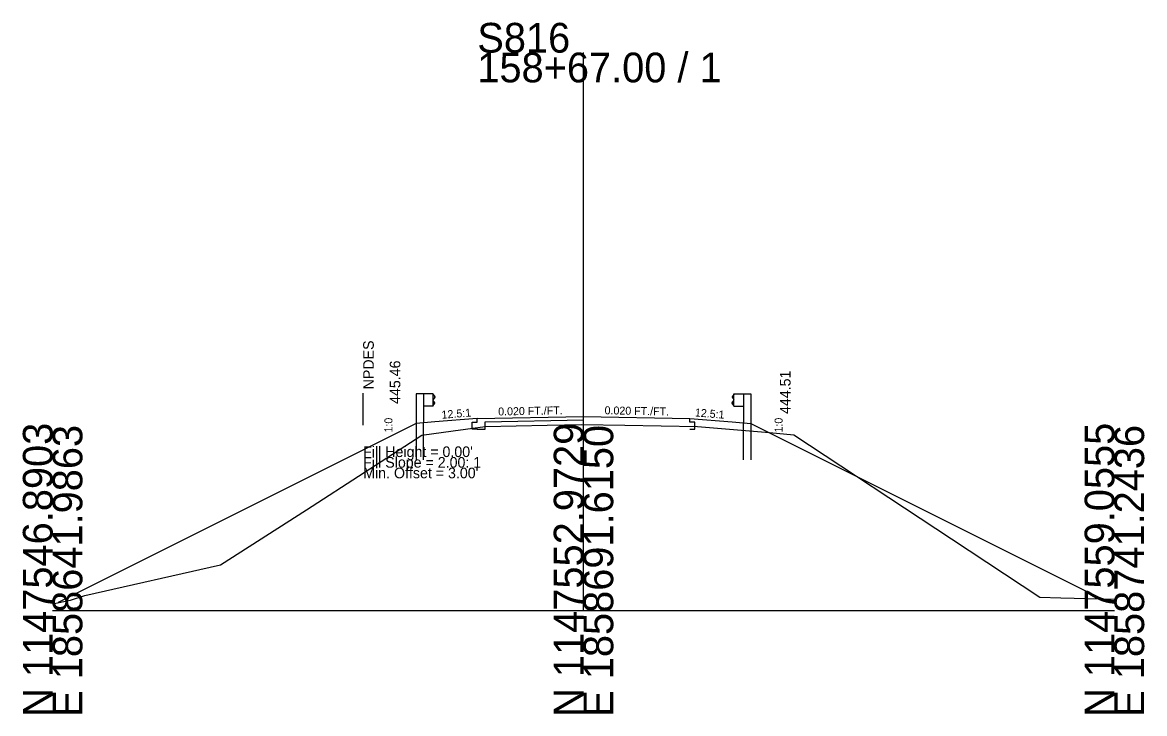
# Model space of a CAD drawing. Extents: x -76 to 4323, y -10 to 2055.
# Drawn here: x 997.2 to 1102.8, y -9.7 to 55.4 of the extents above; entities that cross this region are included whole.
import ezdxf

# ---------------------------------------------------------------- set-up
doc = ezdxf.new("R2010")
doc.units = 0
for name, color, linetype in [('Default', 7, 'Continuous'), ('RD_GPK_XS_Cell', 7, 'Continuous'), ('RD_XS_Base', 7, 'Continuous'), ('RD_XS_Buildup', 7, 'Continuous'), ('RD_XS_EarthShd', 7, 'Continuous'), ('RD_XS_ExGround', 7, 'Continuous'), ('RD_XS_GR', 7, 'Continuous'), ('RD_XS_NPDES', 7, 'Continuous'), ('RD_XS_Pave', 7, 'Continuous'), ('RD_XS_TieSlope', 7, 'Continuous'), ('RD_XS_TX_Elev_PR', 7, 'Continuous'), ('RD_XS_TX_ShdSlope', 7, 'Continuous'), ('RD_XS_TX_Slope', 7, 'Continuous'), ('RD_XS_TX_Warning', 7, 'Continuous')]:
    doc.layers.add(name, color=color, linetype=linetype)

msp = doc.modelspace()

# ---------------------------------------------------------------- linework, layer by layer
at = {"layer": 'Default'}
for p, q in [((1040, 18.08), (1050, 18.28)), ((1050, 18.28), (1060, 18.08))]:
    msp.add_line(p, q, dxfattribs=at)
at = {"layer": 'RD_GPK_XS_Cell'}
for p, q in [((1050, 0), (1050, 52.54)), ((1000, 0), (1050, 0)), ((1050, 0), (1100, 0))]:
    msp.add_line(p, q, dxfattribs=at)
at = {"layer": 'RD_XS_Base'}
for p, q in [((1040, 17.08), (1040.73, 17.09)), ((1040, 17.08), (1040.73, 17.09)), ((1040.73, 17.09), (1040.73, 17.33)), ((1040.73, 17.09), (1040.73, 17.33))]:
    msp.add_line(p, q, dxfattribs=at)
at = {"layer": 'RD_XS_Buildup'}
for p, q in [((1040.73, 17.76), (1050, 17.95)), ((1040.73, 17.76), (1050, 17.95)), ((1040.73, 17.33), (1040.73, 17.76)), ((1040.73, 17.33), (1040.73, 17.76))]:
    msp.add_line(p, q, dxfattribs=at)
at = {"layer": 'RD_XS_EarthShd'}
for p, q in [((1040, 18.08), (1036, 17.76)), ((1040, 18.08), (1036, 17.76)), ((1060, 18.08), (1064, 17.76)), ((1060, 18.08), (1064, 17.76)), ((1036, 17.76), (1034.25, 17.62)), ((1064, 17.76), (1065.75, 17.62))]:
    msp.add_line(p, q, dxfattribs=at)
at = {"layer": 'RD_XS_ExGround'}
for p, q in [((1034.78, 16.53), (1037.73, 16.92)), ((1037.73, 16.92), (1040.73, 17.33)), ((1040.73, 17.33), (1046.57, 17.46)), ((1046.57, 17.46), (1049.85, 17.51)), ((1049.85, 17.51), (1053.88, 17.46)), ((1053.88, 17.46), (1060.75, 17.34)), ((1060.75, 17.34), (1067.52, 16.76)), ((1023.9, 9.49), (1034.78, 16.53)), ((1067.52, 16.76), (1069.82, 16.56)), ((1069.82, 16.56), (1084.67, 6.77)), ((1015.82, 4.3), (1023.9, 9.49)), ((1084.67, 6.77), (1092.97, 1.26)), ((1003.04, 1.42), (1015.82, 4.3)), ((1001.68, 0.99), (1003.04, 1.42)), ((1092.97, 1.26), (1094.95, 1.21)), ((1094.95, 1.21), (1100, 1.08)), ((1000, 0.65), (1001.68, 0.99))]:
    msp.add_line(p, q, dxfattribs=at)
at = {"layer": 'RD_XS_GR'}
for p, q in [((1034.25, 20.42), (1034.25, 17.62)), ((1034.92, 20.42), (1034.25, 20.42)), ((1034.25, 20.42), (1034.25, 17.62)), ((1034.92, 20.42), (1034.25, 20.42)), ((1034.92, 20.42), (1034.92, 17.67)), ((1035.83, 20.42), (1034.92, 20.42)), ((1034.92, 20.42), (1034.92, 17.67)), ((1035.83, 20.42), (1034.92, 20.42)), ((1035.83, 19.25), (1035.83, 20.42)), ((1035.83, 19.25), (1035.83, 20.42)), ((1035.83, 20.34), (1036, 20.14)), ((1035.83, 20.34), (1036, 20.14)), ((1036, 20.09), (1035.83, 19.89)), ((1036, 20.09), (1035.83, 19.89)), ((1036, 20.14), (1036, 20.09)), ((1036, 20.14), (1036, 20.09)), ((1064.17, 20.34), (1064, 20.14)), ((1064.17, 20.34), (1064, 20.14)), ((1064, 20.14), (1064, 20.09)), ((1064, 20.14), (1064, 20.09)), ((1064, 20.09), (1064.17, 19.89)), ((1064, 20.09), (1064.17, 19.89)), ((1064.17, 20.42), (1065.08, 20.42)), ((1064.17, 19.25), (1064.17, 20.42)), ((1064.17, 20.42), (1065.08, 20.42)), ((1064.17, 19.25), (1064.17, 20.42)), ((1065.08, 20.42), (1065.75, 20.42)), ((1065.08, 20.42), (1065.08, 17.67)), ((1065.08, 20.42), (1065.75, 20.42)), ((1065.08, 20.42), (1065.08, 17.67)), ((1065.75, 20.42), (1065.75, 17.62)), ((1065.75, 20.42), (1065.75, 17.62)), ((1035.83, 19.25), (1034.92, 19.25)), ((1035.83, 19.25), (1034.92, 19.25)), ((1036, 19.57), (1035.83, 19.77)), ((1036, 19.57), (1035.83, 19.77)), ((1035.83, 19.32), (1036, 19.52)), ((1035.83, 19.32), (1036, 19.52)), ((1036, 19.52), (1036, 19.57)), ((1036, 19.52), (1036, 19.57)), ((1064, 19.57), (1064.17, 19.77)), ((1064, 19.57), (1064.17, 19.77)), ((1064, 19.52), (1064, 19.57)), ((1064, 19.52), (1064, 19.57)), ((1064.17, 19.32), (1064, 19.52)), ((1064.17, 19.32), (1064, 19.52)), ((1064.17, 19.25), (1065.08, 19.25)), ((1064.17, 19.25), (1065.08, 19.25)), ((1034.25, 17.62), (1034.25, 14.2)), ((1034.25, 17.62), (1034.25, 14.2)), ((1034.92, 14.2), (1034.92, 17.67)), ((1034.92, 14.2), (1034.92, 17.67)), ((1065.08, 14.2), (1065.08, 17.67)), ((1065.08, 14.2), (1065.08, 17.67)), ((1065.75, 17.62), (1065.75, 14.2)), ((1065.75, 17.62), (1065.75, 14.2))]:
    msp.add_line(p, q, dxfattribs=at)
at = {"layer": 'RD_XS_NPDES'}
msp.add_line((1029.25, 17.46), (1029.25, 20.46), dxfattribs=at)
msp.add_line((1029.25, 17.46), (1029.25, 20.46), dxfattribs=at)
at = {"layer": 'RD_XS_Pave'}
for p, q in [((1040, 17.75), (1040, 18.08)), ((1040, 17.75), (1040, 18.08)), ((1060, 17.75), (1060, 18.08)), ((1060, 17.75), (1060, 18.08)), ((1039.5, 17.74), (1040, 17.75)), ((1039.5, 17.74), (1040, 17.75)), ((1039.5, 17.07), (1039.5, 17.74)), ((1039.5, 17.07), (1039.5, 17.74)), ((1040, 17.08), (1039.5, 17.07)), ((1040, 17.08), (1039.5, 17.07)), ((1060.5, 17.74), (1060, 17.75)), ((1060.5, 17.74), (1060, 17.75)), ((1060, 17.08), (1060.5, 17.07)), ((1060, 17.08), (1060.5, 17.07)), ((1060.5, 17.07), (1060.5, 17.74)), ((1060.5, 17.07), (1060.5, 17.74))]:
    msp.add_line(p, q, dxfattribs=at)
at = {"layer": 'RD_XS_TieSlope'}
for p, q in [((1034.25, 17.62), (1000.52, 0.76)), ((1065.75, 17.62), (1098.77, 1.11))]:
    msp.add_line(p, q, dxfattribs=at)

# ---------------------------------------------------------------- texts
at = {"layer": 'RD_GPK_XS_Cell'}
for s, p in [('S816', (1040, 52.54)), ('158+67.00 / 1', (1040, 49.74))]:
    msp.add_text(s, height=2.8, dxfattribs=at).set_placement(p)
for s, p in [('N 1147546.8903', (1000, -10)), ('E 1858641.9863', (1002.8, -10)), ('N 1147552.9729', (1050, -10)), ('E 1858691.6150', (1052.8, -10)), ('N 1147559.0555', (1100, -10)), ('E 1858741.2436', (1102.8, -10))]:
    msp.add_text(s, height=2.8, rotation=90, dxfattribs=at).set_placement(p)
at = {"layer": 'RD_XS_TX_Elev_PR'}
for s, p in [('445.46', (1032.75, 19.46)), ('445.46', (1032.75, 19.46)), ('444.51', (1069.5, 18.51)), ('444.51', (1069.5, 18.51))]:
    msp.add_text(s, height=1, rotation=90, dxfattribs=at).set_placement(p)
at = {"layer": 'RD_XS_TX_ShdSlope'}
for rotation, p in [(4.5739, (1036.66, 18.06)), (4.5739, (1036.66, 18.06)), (355.4261, (1060.47, 18.29)), (355.4261, (1060.47, 18.29))]:
    msp.add_text('12.5:1', height=0.75, rotation=rotation, dxfattribs=at).set_placement(p)
at = {"layer": 'RD_XS_TX_Slope'}
for s, rotation, p in [('0.020 FT./FT.', 1.1458, (1041.97, 18.37)), ('0.020 FT./FT.', 1.1458, (1041.97, 18.37)), ('0.020 FT./FT.', 358.8542, (1051.98, 18.49)), ('0.020 FT./FT.', 358.8542, (1051.98, 18.49)), ('1:0', 90, (1032, 16.77)), ('1:0', 90, (1032, 16.77)), ('1:0', 90, (1068.75, 16.77))]:
    msp.add_text(s, height=0.75, rotation=rotation, dxfattribs=at).set_placement(p)
at = {"layer": 'RD_XS_TX_Warning'}
msp.add_text(' NPDES', height=1, rotation=90, dxfattribs=at).set_placement((1030.25, 20.46))
msp.add_text(' NPDES', height=1, rotation=90, dxfattribs=at).set_placement((1030.25, 20.46))
for s, p in [("Fill Height = 0.00' ", (1029.25, 14.46)), ("Fill Height = 0.00' ", (1029.25, 14.46)), ('Fill Slope = 2.00: 1', (1029.25, 13.46)), ('Fill Slope = 2.00: 1', (1029.25, 13.46)), ("Min. Offset = 3.00' ", (1029.25, 12.46)), ("Min. Offset = 3.00' ", (1029.25, 12.46))]:
    msp.add_text(s, height=1, dxfattribs=at).set_placement(p)

doc.saveas('drawing.dxf')
